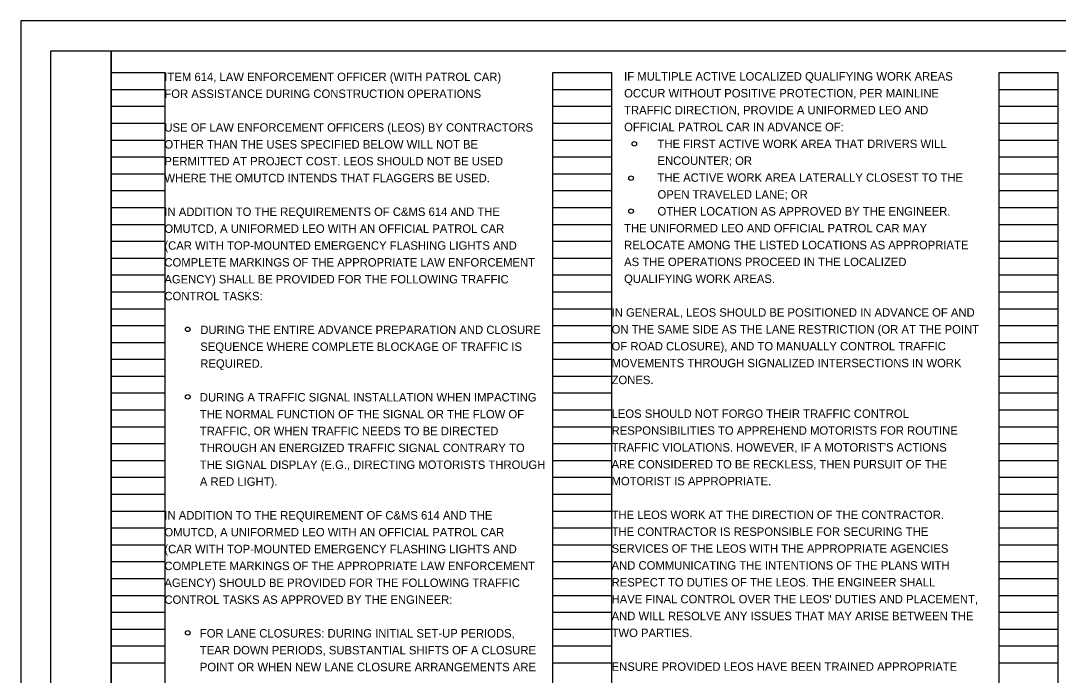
# Model space of a CAD drawing. Extents: x 0.1 to 34.1, y 0.1 to 22.1.
# Drawn here: x 0.08 to 17.32, y 11.23 to 22.1 of the extents above; entities that cross this region are included whole.
import ezdxf

# ---------------------------------------------------------------- set-up
doc = ezdxf.new("R2010")
doc.units = 0
for name, color, linetype in [('SH_Border', 7, 'Continuous'), ('SH_Cut_Line', 7, 'Continuous'), ('SH_Data', 7, 'Continuous'), ('SH_Text', 7, 'Continuous')]:
    doc.layers.add(name, color=color, linetype=linetype)

msp = doc.modelspace()

# ---------------------------------------------------------------- linework, layer by layer
at = {"layer": 'SH_Border'}
for points in [[(0.576, 21.599), (1.576, 21.599), (1.576, 0.599), (0.576, 0.599)], [(1.576, 21.599), (33.576, 21.599), (33.576, 0.599), (1.576, 0.599)]]:
    msp.add_lwpolyline(points, close=True, dxfattribs=at)
at = {"layer": 'SH_Cut_Line'}
msp.add_lwpolyline([(0.076, 0.099), (34.076, 0.099), (34.076, 22.099), (0.076, 22.099)], close=True, dxfattribs=at)
at = {"layer": 'SH_Data'}
for p, q in [((1.576, 1.079), (1.576, 21.239)), ((1.576, 21.239), (2.476, 21.239)), ((2.476, 1.079), (2.476, 21.239)), ((8.916, 1.079), (8.916, 21.239)), ((8.916, 21.239), (9.896, 21.239)), ((9.896, 1.079), (9.896, 21.239)), ((16.336, 1.079), (16.336, 21.239)), ((16.336, 21.239), (17.316, 21.239)), ((17.316, 1.079), (17.316, 21.239)), ((1.576, 20.959), (2.476, 20.959)), ((8.916, 20.959), (9.896, 20.959)), ((16.336, 20.959), (17.316, 20.959)), ((1.576, 20.679), (2.476, 20.679)), ((8.916, 20.679), (9.896, 20.679)), ((16.336, 20.679), (17.316, 20.679)), ((1.576, 20.399), (2.476, 20.399)), ((8.916, 20.399), (9.896, 20.399)), ((16.336, 20.399), (17.316, 20.399)), ((1.576, 20.119), (2.476, 20.119)), ((8.916, 20.119), (9.896, 20.119)), ((16.336, 20.119), (17.316, 20.119)), ((1.576, 19.839), (2.476, 19.839)), ((8.916, 19.839), (9.896, 19.839)), ((16.336, 19.839), (17.316, 19.839)), ((1.576, 19.559), (2.476, 19.559)), ((8.916, 19.559), (9.896, 19.559)), ((16.336, 19.559), (17.316, 19.559)), ((1.576, 19.279), (2.476, 19.279)), ((8.916, 19.279), (9.896, 19.279)), ((16.336, 19.279), (17.316, 19.279)), ((1.576, 18.999), (2.476, 18.999)), ((8.916, 18.999), (9.896, 18.999)), ((16.336, 18.999), (17.316, 18.999)), ((1.576, 18.719), (2.476, 18.719)), ((8.916, 18.719), (9.896, 18.719)), ((16.336, 18.719), (17.316, 18.719)), ((1.576, 18.439), (2.476, 18.439)), ((8.916, 18.439), (9.896, 18.439)), ((16.336, 18.439), (17.316, 18.439)), ((1.576, 18.159), (2.476, 18.159)), ((8.916, 18.159), (9.896, 18.159)), ((16.336, 18.159), (17.316, 18.159)), ((1.576, 17.879), (2.476, 17.879)), ((8.916, 17.879), (9.896, 17.879)), ((16.336, 17.879), (17.316, 17.879)), ((1.576, 17.599), (2.476, 17.599)), ((8.916, 17.599), (9.896, 17.599)), ((16.336, 17.599), (17.316, 17.599)), ((1.576, 17.319), (2.476, 17.319)), ((8.916, 17.319), (9.896, 17.319)), ((16.336, 17.319), (17.316, 17.319)), ((1.576, 17.039), (2.476, 17.039)), ((8.916, 17.039), (9.896, 17.039)), ((16.336, 17.039), (17.316, 17.039)), ((1.576, 16.759), (2.476, 16.759)), ((8.916, 16.759), (9.896, 16.759)), ((16.336, 16.759), (17.316, 16.759)), ((1.576, 16.479), (2.476, 16.479)), ((8.916, 16.479), (9.896, 16.479)), ((16.336, 16.479), (17.316, 16.479)), ((1.576, 16.199), (2.476, 16.199)), ((8.916, 16.199), (9.896, 16.199)), ((16.336, 16.199), (17.316, 16.199)), ((1.576, 15.919), (2.476, 15.919)), ((8.916, 15.919), (9.896, 15.919)), ((16.336, 15.919), (17.316, 15.919)), ((1.576, 15.639), (2.476, 15.639)), ((8.916, 15.639), (9.896, 15.639)), ((16.336, 15.639), (17.316, 15.639)), ((1.576, 15.359), (2.476, 15.359)), ((8.916, 15.359), (9.896, 15.359)), ((16.336, 15.359), (17.316, 15.359)), ((1.576, 15.079), (2.476, 15.079)), ((8.916, 15.079), (9.896, 15.079)), ((16.336, 15.079), (17.316, 15.079)), ((1.576, 14.799), (2.476, 14.799)), ((8.916, 14.799), (9.896, 14.799)), ((16.336, 14.799), (17.316, 14.799)), ((1.576, 14.519), (2.476, 14.519)), ((8.916, 14.519), (9.896, 14.519)), ((16.336, 14.519), (17.316, 14.519)), ((1.576, 14.239), (2.476, 14.239)), ((8.916, 14.239), (9.896, 14.239)), ((16.336, 14.239), (17.316, 14.239)), ((1.576, 13.959), (2.476, 13.959)), ((8.916, 13.959), (9.896, 13.959)), ((16.336, 13.959), (17.316, 13.959)), ((1.576, 13.679), (2.476, 13.679)), ((8.916, 13.679), (9.896, 13.679)), ((16.336, 13.679), (17.316, 13.679)), ((1.576, 13.399), (2.476, 13.399)), ((8.916, 13.399), (9.896, 13.399)), ((16.336, 13.399), (17.316, 13.399)), ((1.576, 13.119), (2.476, 13.119)), ((8.916, 13.119), (9.896, 13.119)), ((16.336, 13.119), (17.316, 13.119)), ((1.576, 12.839), (2.476, 12.839)), ((8.916, 12.839), (9.896, 12.839)), ((16.336, 12.839), (17.316, 12.839)), ((1.576, 12.559), (2.476, 12.559)), ((8.916, 12.559), (9.896, 12.559)), ((16.336, 12.559), (17.316, 12.559)), ((1.576, 12.279), (2.476, 12.279)), ((8.916, 12.279), (9.896, 12.279)), ((16.336, 12.279), (17.316, 12.279)), ((1.576, 11.999), (2.476, 11.999)), ((8.916, 11.999), (9.896, 11.999)), ((16.336, 11.999), (17.316, 11.999)), ((1.576, 11.719), (2.476, 11.719)), ((8.916, 11.719), (9.896, 11.719)), ((16.336, 11.719), (17.316, 11.719)), ((1.576, 11.439), (2.476, 11.439)), ((8.916, 11.439), (9.896, 11.439)), ((16.336, 11.439), (17.316, 11.439))]:
    msp.add_line(p, q, dxfattribs=at)
at = {"layer": 'SH_Text'}
for centre in [(10.271, 20.056), (10.218, 19.487), (10.218, 18.938), (2.851, 16.976), (2.851, 15.856), (2.851, 11.936)]:
    msp.add_circle(centre, 0.0378, dxfattribs=at)

# ---------------------------------------------------------------- texts
for s, p in [('ITEM 614, LAW ENFORCEMENT OFFICER (WITH PATROL CAR)', (2.463, 21.098)), ('    IF MULTIPLE ACTIVE LOCALIZED QUALIFYING WORK AREAS', (9.894, 21.106)), ('FOR ASSISTANCE DURING CONSTRUCTION OPERATIONS', (2.463, 20.818)), ('    OCCUR WITHOUT POSITIVE PROTECTION, PER MAINLINE', (9.894, 20.826)), ('    TRAFFIC DIRECTION, PROVIDE A UNIFORMED LEO AND', (9.894, 20.546)), ('USE OF LAW ENFORCEMENT OFFICERS (LEOS) BY CONTRACTORS', (2.463, 20.258)), ('    OFFICIAL PATROL CAR IN ADVANCE OF:', (9.894, 20.266)), ('OTHER THAN THE USES SPECIFIED BELOW WILL NOT BE', (2.463, 19.978)), ('        THE FIRST ACTIVE WORK AREA THAT DRIVERS WILL', (10.241, 19.986)), ('PERMITTED AT PROJECT COST. LEOS SHOULD NOT BE USED', (2.463, 19.698)), ('        ENCOUNTER; OR', (10.241, 19.706)), ('WHERE THE OMUTCD INTENDS THAT FLAGGERS BE USED.', (2.463, 19.418)), ('        THE ACTIVE WORK AREA LATERALLY CLOSEST TO THE', (10.241, 19.426)), ('        OPEN TRAVELED LANE; OR', (10.241, 19.146)), ('IN ADDITION TO THE REQUIREMENTS OF C&MS 614 AND THE', (2.463, 18.858)), ('        OTHER LOCATION AS APPROVED BY THE ENGINEER.', (10.241, 18.866)), ('OMUTCD, A UNIFORMED LEO WITH AN OFFICIAL PATROL CAR', (2.463, 18.578)), ('    THE UNIFORMED LEO AND OFFICIAL PATROL CAR MAY', (9.894, 18.586)), ('    RELOCATE AMONG THE LISTED LOCATIONS AS APPROPRIATE', (9.894, 18.306)), ('(CAR WITH TOP-MOUNTED EMERGENCY FLASHING LIGHTS AND', (2.463, 18.298)), ('COMPLETE MARKINGS OF THE APPROPRIATE LAW ENFORCEMENT', (2.463, 18.018)), ('    AS THE OPERATIONS PROCEED IN THE LOCALIZED', (9.894, 18.026)), ('AGENCY) SHALL BE PROVIDED FOR THE FOLLOWING TRAFFIC', (2.463, 17.738)), ('    QUALIFYING WORK AREAS.', (9.894, 17.746)), ('CONTROL TASKS:', (2.463, 17.458)), ('IN GENERAL, LEOS SHOULD BE POSITIONED IN ADVANCE OF AND', (9.894, 17.186)), ('    DURING THE ENTIRE ADVANCE PREPARATION AND CLOSURE', (2.851, 16.898)), ('ON THE SAME SIDE AS THE LANE RESTRICTION (OR AT THE POINT', (9.894, 16.906)), ('    SEQUENCE WHERE COMPLETE BLOCKAGE OF TRAFFIC IS', (2.851, 16.618)), ('OF ROAD CLOSURE), AND TO MANUALLY CONTROL TRAFFIC', (9.894, 16.626)), ('    REQUIRED.', (2.851, 16.338)), ('MOVEMENTS THROUGH SIGNALIZED INTERSECTIONS IN WORK', (9.894, 16.346)), ('ZONES.', (9.894, 16.066)), ('    DURING A TRAFFIC SIGNAL INSTALLATION WHEN IMPACTING', (2.844, 15.778)), ('    THE NORMAL FUNCTION OF THE SIGNAL OR THE FLOW OF', (2.844, 15.498)), ('LEOS SHOULD NOT FORGO THEIR TRAFFIC CONTROL', (9.894, 15.506)), ('    TRAFFIC, OR WHEN TRAFFIC NEEDS TO BE DIRECTED', (2.844, 15.218)), ('RESPONSIBILITIES TO APPREHEND MOTORISTS FOR ROUTINE', (9.894, 15.226)), ('    THROUGH AN ENERGIZED TRAFFIC SIGNAL CONTRARY TO', (2.844, 14.938)), ("TRAFFIC VIOLATIONS. HOWEVER, IF A MOTORIST'S ACTIONS", (9.894, 14.946)), ('    THE SIGNAL DISPLAY (E.G., DIRECTING MOTORISTS THROUGH', (2.844, 14.658)), ('ARE CONSIDERED TO BE RECKLESS, THEN PURSUIT OF THE', (9.894, 14.666)), ('    A RED LIGHT).', (2.844, 14.378)), ('MOTORIST IS APPROPRIATE.', (9.894, 14.386)), ('THE LEOS WORK AT THE DIRECTION OF THE CONTRACTOR.', (9.894, 13.826)), ('IN ADDITION TO THE REQUIREMENT OF C&MS 614 AND THE', (2.463, 13.818)), ('OMUTCD, A UNIFORMED LEO WITH AN OFFICIAL PATROL CAR', (2.463, 13.538)), ('THE CONTRACTOR IS RESPONSIBLE FOR SECURING THE', (9.894, 13.546)), ('(CAR WITH TOP-MOUNTED EMERGENCY FLASHING LIGHTS AND', (2.463, 13.258)), ('SERVICES OF THE LEOS WITH THE APPROPRIATE AGENCIES', (9.894, 13.266)), ('COMPLETE MARKINGS OF THE APPROPRIATE LAW ENFORCEMENT', (2.463, 12.978)), ('AND COMMUNICATING THE INTENTIONS OF THE PLANS WITH', (9.894, 12.986)), ('AGENCY) SHOULD BE PROVIDED FOR THE FOLLOWING TRAFFIC', (2.463, 12.698)), ('RESPECT TO DUTIES OF THE LEOS. THE ENGINEER SHALL', (9.894, 12.706)), ('CONTROL TASKS AS APPROVED BY THE ENGINEER:', (2.463, 12.418)), ("HAVE FINAL CONTROL OVER THE LEOS' DUTIES AND PLACEMENT,", (9.894, 12.426)), ('AND WILL RESOLVE ANY ISSUES THAT MAY ARISE BETWEEN THE', (9.894, 12.146)), ('    FOR LANE CLOSURES: DURING INITIAL SET-UP PERIODS,', (2.844, 11.859)), ('TWO PARTIES.', (9.894, 11.866)), ('    TEAR DOWN PERIODS, SUBSTANTIAL SHIFTS OF A CLOSURE', (2.844, 11.579)), ('    POINT OR WHEN NEW LANE CLOSURE ARRANGEMENTS ARE', (2.844, 11.299)), ('ENSURE PROVIDED LEOS HAVE BEEN TRAINED APPROPRIATE', (9.894, 11.306))]:
    msp.add_text(s, height=0.14, dxfattribs=at).set_placement(p)

doc.saveas('drawing.dxf')
